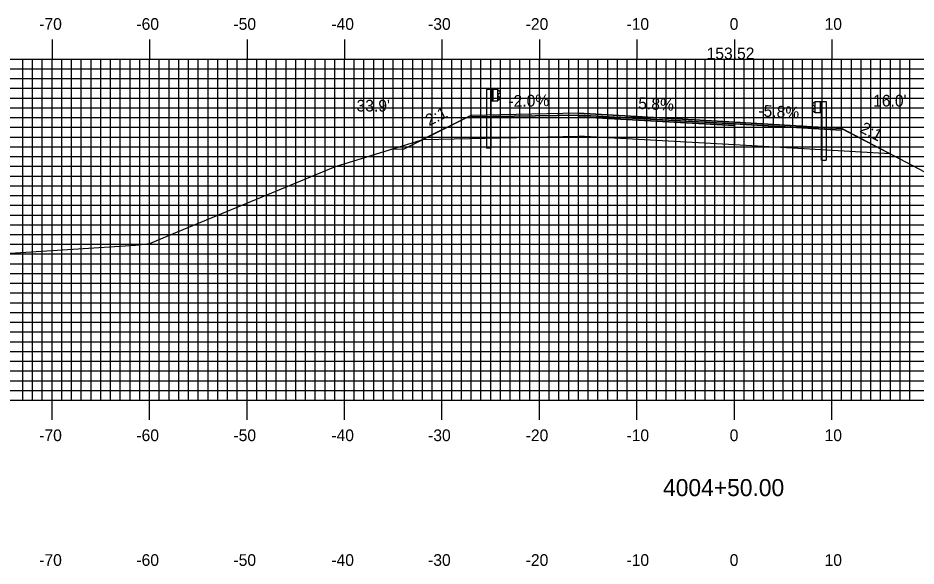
# Model space of a CAD drawing. Extents: x 850966 to 851310, y 364661 to 364881.
# Drawn here: x 851058.7 to 851150.9, y 364727.4 to 364783.6 of the extents above; entities that cross this region are included whole.
import ezdxf

# ---------------------------------------------------------------- set-up
doc = ezdxf.new("R2010")
doc.units = 0
for name, color, linetype in [('ANNOTATION', 7, 'Continuous'), ('D_Guardrail_Beam_Lt', 7, 'Continuous'), ('D_Guardrail_Beam_Rt', 7, 'Continuous'), ('D_Roadway_Centerline_Text', 7, 'Continuous'), ('D_Roadway_Edge_Shoulder', 7, 'Continuous'), ('D_Roadway_Edge_TW', 7, 'Continuous'), ('D_Roadway_Pavement', 7, 'Continuous'), ('D_Roadway_SlopeLines', 7, 'Continuous'), ('D_Roadway_SubGrade', 7, 'Continuous'), ('D_Text_Standard', 7, 'Continuous'), ('H_V ANNOTATION', 7, 'Continuous'), ('M_Roadway_Centerline', 7, 'Continuous'), ('MAJOR', 7, 'Continuous'), ('MINOR', 7, 'Continuous'), ('S_Roadway_Centerline', 7, 'Continuous')]:
    doc.layers.add(name, color=color, linetype=linetype)

msp = doc.modelspace()

# ---------------------------------------------------------------- linework, layer by layer
at = {"layer": 'D_Guardrail_Beam_Lt'}
for p, q in [((851106.787, 364776.239), (851106.787, 364770.239)), ((851107.257, 364776.239), (851106.787, 364776.239)), ((851107.945, 364776.239), (851107.257, 364776.239)), ((851107.257, 364776.239), (851107.257, 364775.072)), ((851107.32, 364776.239), (851107.32, 364775.072)), ((851107.424, 364776.239), (851107.424, 364775.072)), ((851107.945, 364775.072), (851107.945, 364776.239)), ((851107.945, 364776.156), (851108.019, 364776.141)), ((851107.949, 364775.691), (851107.949, 364775.621)), ((851108.178, 364775.891), (851107.983, 364775.755)), ((851107.983, 364775.556), (851108.178, 364775.42)), ((851108.035, 364776.134), (851108.178, 364776.034)), ((851107.257, 364775.072), (851107.945, 364775.072)), ((851107.278, 364770.239), (851107.278, 364775.072)), ((851108.019, 364775.17), (851107.945, 364775.156)), ((851108.178, 364775.277), (851108.035, 364775.177)), ((851107.278, 364770.239), (851106.787, 364770.239))]:
    msp.add_line(p, q, dxfattribs=at)
for centre, major_axis, start_param, end_param in [((851108.028, 364775.691), (-0.0789, 0), 5.323254, 6.283185), ((851108.028, 364775.621), (-0.0789, 0), 6.283185, 7.243116), ((851108.011, 364776.1), (0.0417, 0), 0.959931, 1.376053), ((851108.128, 364775.963), (0.0877, 0), 5.323254, 7.243116), ((851108.011, 364775.211), (0.0417, 0), 4.907132, 5.323254), ((851108.128, 364775.349), (0.0877, 0), 5.323254, 7.243116)]:
    msp.add_ellipse(centre, major_axis=major_axis, ratio=0.995501, start_param=start_param, end_param=end_param, dxfattribs=at)
at = {"layer": 'D_Guardrail_Beam_Rt'}
for p, q in [((851140.397, 364774.902), (851140.253, 364774.802)), ((851140.253, 364774.659), (851140.449, 364774.523)), ((851140.487, 364774.924), (851140.412, 364774.909)), ((851140.487, 364775.007), (851141.174, 364775.007)), ((851140.487, 364773.84), (851140.487, 364775.007)), ((851141.007, 364775.007), (851141.007, 364773.84)), ((851141.112, 364775.007), (851141.112, 364773.84)), ((851141.174, 364775.007), (851141.645, 364775.007)), ((851141.174, 364775.007), (851141.174, 364773.84)), ((851141.645, 364775.007), (851141.645, 364769.007)), ((851140.449, 364774.324), (851140.253, 364774.188)), ((851140.253, 364774.045), (851140.397, 364773.945)), ((851140.412, 364773.938), (851140.487, 364773.924)), ((851140.482, 364774.459), (851140.482, 364774.389)), ((851141.174, 364773.84), (851140.487, 364773.84)), ((851141.153, 364769.007), (851141.153, 364773.84)), ((851141.153, 364769.007), (851141.645, 364769.007))]:
    msp.add_line(p, q, dxfattribs=at)
for centre, major_axis, start_param, end_param in [((851140.304, 364774.731), (-0.0877, 0), 5.323254, 7.243116), ((851140.421, 364774.868), (-0.0417, 0), 4.907132, 5.323254), ((851140.403, 364774.459), (0.0789, 0), 0, 0.959931), ((851140.304, 364774.117), (-0.0877, 0), 5.323254, 7.243116), ((851140.421, 364773.979), (-0.0417, 0), 0.959931, 1.376053), ((851140.403, 364774.389), (0.0789, 0), 5.323254, 6.283185)]:
    msp.add_ellipse(centre, major_axis=major_axis, ratio=0.995501, start_param=start_param, end_param=end_param, dxfattribs=at)
at = {"layer": 'D_Roadway_Edge_Shoulder'}
for points in [[(851116.216, 364773.816), (851108.216, 364773.656), (851108.216, 364773.656), (851105.216, 364773.596), (851105.216, 364773.429), (851116.216, 364773.617)], [(851132.216, 364772.888), (851140.216, 364772.424), (851140.216, 364772.424), (851143.216, 364772.25), (851143.216, 364772.083), (851132.216, 364772.721)]]:
    msp.add_lwpolyline(points, close=True, dxfattribs=at)
at = {"layer": 'D_Roadway_Edge_TW'}
msp.add_lwpolyline([(851116.216, 364773.816), (851132.216, 364772.888), (851132.216, 364772.721), (851116.216, 364773.617)], close=True, dxfattribs=at)
at = {"layer": 'D_Roadway_Pavement'}
msp.add_lwpolyline([(851116.216, 364773.617), (851132.216, 364772.721), (851132.216, 364772.554), (851116.216, 364773.45)], close=True, dxfattribs=at)
for points in [[(851116.216, 364773.617), (851116.216, 364773.45)], [(851132.216, 364772.721), (851132.216, 364772.554)], [(851132.216, 364772.721), (851132.216, 364772.554)], [(851132.216, 364772.721), (851132.216, 364772.554)]]:
    msp.add_lwpolyline(points, dxfattribs=at)
at = {"layer": 'D_Roadway_SlopeLines'}
for points in [[(851105.216, 364773.596), (851100.185, 364771.08)], [(851100.288, 364771.132), (851098.288, 364770.132), (851096.966, 364770.105)]]:
    msp.add_lwpolyline(points, dxfattribs=at)
at = {"layer": 'D_Roadway_SubGrade'}
msp.add_line((851143.216, 364772.25), (851148.198, 364769.66), dxfattribs=at)
for points in [[(851116.216, 364773.45), (851116.216, 364773.617), (851105.216, 364773.429), (851105.216, 364773.596), (851100.288, 364771.132), (851116.216, 364771.45)], [(851116.216, 364773.45), (851132.216, 364772.554), (851132.216, 364770.554), (851116.216, 364771.45)]]:
    msp.add_lwpolyline(points, close=True, dxfattribs=at)
msp.add_lwpolyline([(851148.198, 364769.66), (851132.216, 364770.554), (851132.216, 364772.554), (851132.216, 364772.721), (851143.216, 364772.083), (851143.216, 364772.25)], dxfattribs=at)
at = {"layer": 'MAJOR'}
for p, q in [((851062.216, 364781.374), (851062.216, 364779.37)), ((851072.216, 364781.374), (851072.216, 364779.37)), ((851082.216, 364781.374), (851082.216, 364779.37)), ((851092.216, 364781.374), (851092.216, 364779.37)), ((851102.216, 364781.374), (851102.216, 364779.37)), ((851112.216, 364781.374), (851112.216, 364779.37)), ((851122.216, 364781.374), (851122.216, 364779.37)), ((851132.216, 364781.374), (851132.216, 364779.37)), ((851142.216, 364781.374), (851142.216, 364779.37)), ((850992.216, 364779.37), (851272.216, 364779.37)), ((850992.216, 364779.37), (851272.216, 364779.37)), ((851062.216, 364744.37), (851062.216, 364779.37)), ((851072.216, 364744.37), (851072.216, 364779.37)), ((851082.216, 364744.37), (851082.216, 364779.37)), ((851092.216, 364744.37), (851092.216, 364779.37)), ((851102.216, 364744.37), (851102.216, 364779.37)), ((851112.216, 364744.37), (851112.216, 364779.37)), ((851122.216, 364744.37), (851122.216, 364779.37)), ((851132.216, 364744.37), (851132.216, 364779.37)), ((851142.216, 364744.37), (851142.216, 364779.37)), ((850992.216, 364774.37), (851272.216, 364774.37)), ((850992.216, 364769.37), (851272.216, 364769.37)), ((850992.216, 364764.37), (851272.216, 364764.37)), ((850992.216, 364759.37), (851272.216, 364759.37)), ((850992.216, 364754.37), (851272.216, 364754.37)), ((850992.216, 364749.37), (851272.216, 364749.37)), ((850992.216, 364744.37), (851272.216, 364744.37)), ((850992.216, 364744.37), (851272.216, 364744.37)), ((851062.216, 364742.366), (851062.216, 364744.37)), ((851072.216, 364742.366), (851072.216, 364744.37)), ((851082.216, 364742.366), (851082.216, 364744.37)), ((851092.216, 364742.366), (851092.216, 364744.37)), ((851102.216, 364742.366), (851102.216, 364744.37)), ((851112.216, 364742.366), (851112.216, 364744.37)), ((851122.216, 364742.366), (851122.216, 364744.37)), ((851132.216, 364742.366), (851132.216, 364744.37)), ((851142.216, 364742.366), (851142.216, 364744.37))]:
    msp.add_line(p, q, dxfattribs=at)
at = {"layer": 'MINOR'}
for p, q in [((851059.216, 364744.37), (851059.216, 364779.37)), ((851060.216, 364744.37), (851060.216, 364779.37)), ((851061.216, 364744.37), (851061.216, 364779.37)), ((851063.216, 364744.37), (851063.216, 364779.37)), ((851064.216, 364744.37), (851064.216, 364779.37)), ((851065.216, 364744.37), (851065.216, 364779.37)), ((851066.216, 364744.37), (851066.216, 364779.37)), ((851067.216, 364744.37), (851067.216, 364779.37)), ((851068.216, 364744.37), (851068.216, 364779.37)), ((851069.216, 364744.37), (851069.216, 364779.37)), ((851070.216, 364744.37), (851070.216, 364779.37)), ((851071.216, 364744.37), (851071.216, 364779.37)), ((851073.216, 364744.37), (851073.216, 364779.37)), ((851074.216, 364744.37), (851074.216, 364779.37)), ((851075.216, 364744.37), (851075.216, 364779.37)), ((851076.216, 364744.37), (851076.216, 364779.37)), ((851077.216, 364744.37), (851077.216, 364779.37)), ((851078.216, 364744.37), (851078.216, 364779.37)), ((851079.216, 364744.37), (851079.216, 364779.37)), ((851080.216, 364744.37), (851080.216, 364779.37)), ((851081.216, 364744.37), (851081.216, 364779.37)), ((851083.216, 364744.37), (851083.216, 364779.37)), ((851084.216, 364744.37), (851084.216, 364779.37)), ((851085.216, 364744.37), (851085.216, 364779.37)), ((851086.216, 364744.37), (851086.216, 364779.37)), ((851087.216, 364744.37), (851087.216, 364779.37)), ((851088.216, 364744.37), (851088.216, 364779.37)), ((851089.216, 364744.37), (851089.216, 364779.37)), ((851090.216, 364744.37), (851090.216, 364779.37)), ((851091.216, 364744.37), (851091.216, 364779.37)), ((851093.216, 364744.37), (851093.216, 364779.37)), ((851094.216, 364744.37), (851094.216, 364779.37)), ((851095.216, 364744.37), (851095.216, 364779.37)), ((851096.216, 364744.37), (851096.216, 364779.37)), ((851097.216, 364744.37), (851097.216, 364779.37)), ((851098.216, 364744.37), (851098.216, 364779.37)), ((851099.216, 364744.37), (851099.216, 364779.37)), ((851100.216, 364744.37), (851100.216, 364779.37)), ((851101.216, 364744.37), (851101.216, 364779.37)), ((851103.216, 364744.37), (851103.216, 364779.37)), ((851104.216, 364744.37), (851104.216, 364779.37)), ((851105.216, 364744.37), (851105.216, 364779.37)), ((851106.216, 364744.37), (851106.216, 364779.37)), ((851107.216, 364744.37), (851107.216, 364779.37)), ((851108.216, 364744.37), (851108.216, 364779.37)), ((851109.216, 364744.37), (851109.216, 364779.37)), ((851110.216, 364744.37), (851110.216, 364779.37)), ((851111.216, 364744.37), (851111.216, 364779.37)), ((851113.216, 364744.37), (851113.216, 364779.37)), ((851114.216, 364744.37), (851114.216, 364779.37)), ((851115.216, 364744.37), (851115.216, 364779.37)), ((851116.216, 364744.37), (851116.216, 364779.37)), ((851117.216, 364744.37), (851117.216, 364779.37)), ((851118.216, 364744.37), (851118.216, 364779.37)), ((851119.216, 364744.37), (851119.216, 364779.37)), ((851120.216, 364744.37), (851120.216, 364779.37)), ((851121.216, 364744.37), (851121.216, 364779.37)), ((851123.216, 364744.37), (851123.216, 364779.37)), ((851124.216, 364744.37), (851124.216, 364779.37)), ((851125.216, 364744.37), (851125.216, 364779.37)), ((851126.216, 364744.37), (851126.216, 364779.37)), ((851127.216, 364744.37), (851127.216, 364779.37)), ((851128.216, 364744.37), (851128.216, 364779.37)), ((851129.216, 364744.37), (851129.216, 364779.37)), ((851130.216, 364744.37), (851130.216, 364779.37)), ((851131.216, 364744.37), (851131.216, 364779.37)), ((851133.216, 364744.37), (851133.216, 364779.37)), ((851134.216, 364744.37), (851134.216, 364779.37)), ((851135.216, 364744.37), (851135.216, 364779.37)), ((851136.216, 364744.37), (851136.216, 364779.37)), ((851137.216, 364744.37), (851137.216, 364779.37)), ((851138.216, 364744.37), (851138.216, 364779.37)), ((851139.216, 364744.37), (851139.216, 364779.37)), ((851140.216, 364744.37), (851140.216, 364779.37)), ((851141.216, 364744.37), (851141.216, 364779.37)), ((851143.216, 364744.37), (851143.216, 364779.37)), ((851144.216, 364744.37), (851144.216, 364779.37)), ((851145.216, 364744.37), (851145.216, 364779.37)), ((851146.216, 364744.37), (851146.216, 364779.37)), ((851147.216, 364744.37), (851147.216, 364779.37)), ((851148.216, 364744.37), (851148.216, 364779.37)), ((851149.216, 364744.37), (851149.216, 364779.37)), ((851150.216, 364744.37), (851150.216, 364779.37)), ((850992.216, 364778.37), (851272.216, 364778.37)), ((850992.216, 364777.37), (851272.216, 364777.37)), ((850992.216, 364776.37), (851272.216, 364776.37)), ((850992.216, 364775.37), (851272.216, 364775.37)), ((850992.216, 364773.37), (851272.216, 364773.37)), ((850992.216, 364772.37), (851272.216, 364772.37)), ((850992.216, 364771.37), (851272.216, 364771.37)), ((850992.216, 364770.37), (851272.216, 364770.37)), ((850992.216, 364768.37), (851272.216, 364768.37)), ((850992.216, 364767.37), (851272.216, 364767.37)), ((850992.216, 364766.37), (851272.216, 364766.37)), ((850992.216, 364765.37), (851272.216, 364765.37)), ((850992.216, 364763.37), (851272.216, 364763.37)), ((850992.216, 364762.37), (851272.216, 364762.37)), ((850992.216, 364761.37), (851272.216, 364761.37)), ((850992.216, 364760.37), (851272.216, 364760.37)), ((850992.216, 364758.37), (851272.216, 364758.37)), ((850992.216, 364757.37), (851272.216, 364757.37)), ((850992.216, 364756.37), (851272.216, 364756.37)), ((850992.216, 364755.37), (851272.216, 364755.37)), ((850992.216, 364753.37), (851272.216, 364753.37)), ((850992.216, 364752.37), (851272.216, 364752.37)), ((850992.216, 364751.37), (851272.216, 364751.37)), ((850992.216, 364750.37), (851272.216, 364750.37)), ((850992.216, 364748.37), (851272.216, 364748.37)), ((850992.216, 364747.37), (851272.216, 364747.37)), ((850992.216, 364746.37), (851272.216, 364746.37)), ((850992.216, 364745.37), (851272.216, 364745.37))]:
    msp.add_line(p, q, dxfattribs=at)
at = {"layer": 'S_Roadway_Centerline'}
msp.add_line((851098.288, 364770.132), (851096.966, 364770.105), dxfattribs=at)
for points in [[(850992.216, 364773.228), (850996.402, 364773.219), (850996.774, 364773.269), (850997.039, 364773.54), (850997.367, 364773.908), (850998.22, 364773.832), (850998.685, 364773.724), (851001.23, 364773.249), (851005.364, 364772.569), (851005.43, 364772.663), (851010.852, 364771.204), (851020.906, 364767.957), (851024.959, 364766.921), (851033.566, 364764.91), (851038.257, 364763.645), (851042.074, 364762.929), (851056.289, 364759.338), (851070.769, 364760.283), (851072.231, 364760.455), (851072.973, 364760.743), (851075.083, 364761.652), (851091.309, 364768.334), (851098.604, 364770.618), (851100.03, 364771.035)], [(851100.007, 364771.024), (851100.03, 364771.035), (851105.216, 364773.628), (851108.216, 364773.688), (851116.216, 364773.848), (851132.216, 364772.92), (851140.216, 364772.456), (851143.216, 364772.282), (851148.554, 364769.472), (851174.973, 364755.568)]]:
    msp.add_lwpolyline(points, dxfattribs=at)

# ---------------------------------------------------------------- texts
at = {"layer": 'ANNOTATION'}
for s, rotation, p in [('-2.0%', 1.14576, (851109.038, 364774.458)), ('5.8%', 356.68056, (851122.323, 364774.265)), ('-5.8%', 356.68056, (851134.65, 364773.5)), ('2:1', 26.56505, (851100.897, 364772.472)), ('2:1', 332.53277, (851145.001, 364771.924))]:
    msp.add_text(s, height=1.2, rotation=rotation, dxfattribs=at).set_placement(p)
at = {"layer": 'D_Roadway_Centerline_Text'}
msp.add_text('153.52', height=1.2, dxfattribs=at).set_placement((851129.363, 364779.35))
at = {"layer": 'D_Text_Standard'}
for s, p in [("16.0'", (851146.449, 364774.502)), ("33.9'", (851093.452, 364773.99))]:
    msp.add_text(s, height=1.2, dxfattribs=at).set_placement(p)
at = {"layer": 'H_V ANNOTATION'}
for s, height, p in [('-70', 1.2, (851060.899, 364782.37)), ('-60', 1.2, (851070.867, 364782.37)), ('-50', 1.2, (851080.824, 364782.37)), ('-40', 1.2, (851090.867, 364782.37)), ('-30', 1.2, (851100.792, 364782.37)), ('-20', 1.2, (851110.803, 364782.37)), ('-10', 1.2, (851121.146, 364782.37)), ('0', 1.2, (851131.734, 364782.37)), ('10', 1.2, (851141.467, 364782.37)), ('-70', 1.2, (851060.899, 364740.17)), ('-60', 1.2, (851070.867, 364740.17)), ('-50', 1.2, (851080.824, 364740.17)), ('-40', 1.2, (851090.867, 364740.17)), ('-30', 1.2, (851100.792, 364740.17)), ('-20', 1.2, (851110.803, 364740.17)), ('-10', 1.2, (851121.146, 364740.17)), ('0', 1.2, (851131.734, 364740.17)), ('10', 1.2, (851141.467, 364740.17)), ('4004+50.00', 1.75, (851124.896, 364734.526)), ('-70', 1.2, (851060.899, 364727.37)), ('-60', 1.2, (851070.867, 364727.37)), ('-50', 1.2, (851080.824, 364727.37)), ('-40', 1.2, (851090.867, 364727.37)), ('-30', 1.2, (851100.792, 364727.37)), ('-20', 1.2, (851110.803, 364727.37)), ('-10', 1.2, (851121.146, 364727.37)), ('0', 1.2, (851131.734, 364727.37)), ('10', 1.2, (851141.467, 364727.37))]:
    msp.add_text(s, height=height, dxfattribs=at).set_placement(p)
at = {"layer": 'M_Roadway_Centerline'}
for s, p in [('C', (851120.912, 364772.101)), ('L', (851120.917, 364772.093))]:
    msp.add_text(s, height=0.0146, dxfattribs=at).set_placement(p)

doc.saveas('drawing.dxf')
